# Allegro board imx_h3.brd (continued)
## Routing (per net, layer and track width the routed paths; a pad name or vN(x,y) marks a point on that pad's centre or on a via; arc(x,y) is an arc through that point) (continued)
GND: length 1234.3
  TOP w0.1: 93.23,71.44 92.46,71.44 v1(92.41,71.49) 92.36,71.44 R122.2 ; 93.23,71.44 93.23,71.53 93.24,71.54 FL6.1 ; 93.23,71.44 93.23,71.2 FL7.2 ; 88.45,68.63 88.45,69.09 ; 88.45,69.09 87.75,69.09 v1(87.73,69.1) ; 88.45,69.09 88.45,69.56 ; J13.60 95.91,64.93 ; J13.60 97.68,64.63 v1(97.72,64.68) ; J13.60 94.62,64.63 ; v1(97.51,59.16) 96.98,58.63 J13.36 94.62,58.63 94.02,58.03 C135.2 ; 76.26,87.95 J23.2 ; J23.2 77.25,88.94 ; J23.2 78.23,87.95 ; J23.2 77.25,86.97 ; J13.48 97.62,61.63 v1(97.68,61.69) ; v1(91.7,37.36) 91.7,37.5 92.38,38.19 93.16,38.19 93.17,38.2 93.91,38.2 R57.2 ; J13.SH6 99.14,74.21 ; J13.SH6 98.4,74.21 ; J13.SH6 98.77,76.71 ; J13.SH6 98.77,73.03 v1(99.78,72.03) ; SW5.2 87.16,1.57 ; SW5.2 v1(86.11,0.91) ; SW5.2 87.92,0.91 ; 105.09,70.67 C263.2 105.09,71.6 ; FL8.2 106.01,87.42 v1(106.04,87.39) ; 93.23,80.95 92.39,80.95 v1(92.31,81.03) ; 93.23,80.95 93.23,80.69 FL3.2 ; 93.23,80.95 FL2.1 ; SW3.2 SW3.4 SW7.2 ; SW3.2 93.53,103.61 ; SW3.2 92.57,104.27 ; FL5.2 93.22,75.84 93.22,76.19 ; FL5.2 93,75.82 ; FL5.2 93.47,75.82 ; 93.22,76.19 92.23,76.19 v1(92.19,76.15) ; 93.22,76.19 FL4.1 ; 104.46,55.86 C257.2 ; C257.2 104.46,56.79 ; C257.2 104.93,56.32 ; J13.93 102.72,78.13 103.07,77.79 103.07,77.36 v1(103.13,77.3) ; v1(105.34,98.06) 105.7,97.7 S1.4 ; 52.22,45.05 C66.2 52.69,44.58 ; C108.1 66.51,18.45 R43.2 ; C108.1 66.57,17.53 v1(66.15,17.1) ; C108.1 67.04,18.38 ; C108.1 66.57,18.85 ; 75.78,77.86 C243.2 ; C243.2 76.72,77.86 ; C243.2 76.25,78.33 ; v1(105.34,103.98) 106.66,103.98 ; 106.66,103.98 106.58,103.91 102.06,103.91 SW7.2 ; 106.66,103.98 SW7.4 ; v1(62.64,44.75) 62.2,45.2 61.45,45.2 61.2,44.95 v1(61.02,44.95) ; v1(24.45,27.44) 23.79,28.1 J20.52 ; T1.8 55.82,17.83 ; T1.8 55.82,16.05 ; T1.8 56.71,16.94 ; v1(92.78,69.04) 92.78,69.04 92.78,69.04 93.17,69.43 FL7.1 ; v1(12.99,50.22) 12.98,50.23 12.98,51.79 C217.2 12.97,50.9 12.97,50.9 ; v1(98.2,79.78) 98.77,80.35 J13.SH7 98.77,80.56 ; FL7.1 93.49,69.43 ; FL7.1 93.25,69.05 ; J20.52 J20.50 ; J20.52 22.6,28.1 ; J20.52 23.75,27.64 ; J20.50 J20.48 22.8,29.7 v1(22.37,29.26) ; J20.50 22.67,28.9 22.41,28.64 v1(22.38,28.64) ; FL4.1 92.98,76.49 ; FL4.1 93.45,76.49 ; 77.76,48.42 C2.2 78.23,47.95 ; 12.43,62.91 13.21,62.91 ; 13.21,62.91 13.21,61.17 ; 13.21,62.91 13.21,64.65 ; J20.8 24.49,48.9 25.06,49.47 25.06,49.72 v1(25.11,49.76) ; 111.42,11.19 Y8.2 ; Y8.2 112.17,12.04 ; Y8.2 110.67,12.04 ; Y8.2 111.07,12.39 C148.2 111.31,13.46 v1(111.58,13.19) ; Y8.2 111.42,12.89 ; 93.06,48.94 C262.2 92.59,49.41 ; 76.48,57.77 C246.2 76.48,56.84 ; 82.52,36.76 C277.2 81.08,36.76 ; J13.SH3 99.14,60.56 ; J13.SH3 98.77,63.07 ; J13.SH3 98.5,60.56 98.2,60.86 v1(98.2,61.32) ; J13.SH3 98.77,58.06 ; 71.1,40.4 C113.2 71.1,42.23 ; v1(99.48,68.57) 99.43,68.57 98.77,69.23 J13.SH5 ; 94.02,57.49 C135.2 ; C135.2 93.55,57.96 ; C135.2 94.49,57.96 ; 70.8,52.25 C22.2 70.8,51.31 ; 109.02,7.9 108.55,7.9 108.55,8.36 ; v1(105.27,1.05) 105.6,1.05 105.77,0.88 SW8.1 ; TP3.1 32.73,70.42 ; TP3.1 30.91,70.42 ; TP3.1 31.82,71.33 ; TP3.1 31.82,69.51 ; 26.98,24.86 C239.2 27.91,24.86 ; T1.14 60.32,11.1 ; T1.14 57.93,11.1 ; T1.14 59.13,9.91 ; T1.14 59.13,12.29 ; 108.64,25.98 C300.2 108.64,27.42 ; C256.2 104.33,59.29 104.68,58.94 v1(105.03,58.94) ; C256.2 104.8,59.31 ; C256.2 104.33,59.77 ; SW6.1 98.75,0.89 98.64,1 v1(98.53,1) ; 93.23,83.41 92.26,83.41 v1(92.23,83.38) ; 93.23,83.41 93.23,83.06 FL2.2 ; 93.23,83.41 FL1.1 ; 69.36,49.07 C10.2 ; C10.2 69.36,50 ; C10.2 69.83,49.53 ; J17.3 63.86,31.79 ; J17.3 63.86,29.99 ; J17.3 62.96,30.89 ; J17.3 64.76,30.89 ; C236.2 81.95,8.47 ; C236.2 83.12,7.62 ; C236.2 80.78,7.62 ; 64.16,38.64 64.91,37.88 64.91,37.75 ; v1(99.9,80.42) 100.11,80.64 101.63,80.64 ; FL4.2 93.22,78.65 ; 93.22,78.65 93.22,78.91 FL3.1 ; 93.22,78.65 92.61,78.65 v1(92.51,78.54) ; 66.77,41.72 C100.2 ; C100.2 66.77,42.65 ; C100.2 67.24,42.19 ; 103.96,93.89 S1.3 ; S1.3 105.7,92.36 v1(105.97,92.09) ; S1.3 107.44,93.89 ; S1.3 105.7,94.92 ; v1(61.06,54.37) 61.44,54.74 R58.2 ; v1(98.2,55.54) 98.08,55.54 97.98,55.63 J13.24 ; 75.78,78.99 C244.2 ; C244.2 76.25,78.52 ; C244.2 76.72,78.99 ; R80.2 87.54,44.17 v1(87.06,43.69) ; J13.SH4 98.77,66.87 ; J13.SH4 98.4,65.45 ; J13.SH4 98.77,64.03 ; J13.SH4 99.08,65.45 v1(99.34,65.72) ; J13.23 103.26,55.63 v1(103.28,55.66) ; J13.30 97.98,57.13 98.07,57.05 v1(98.3,57.05) ; 104.65,79.42 104.66,79.41 ; 45.92,59.51 46.39,59.51 ; 45.92,59.51 45.81,59.51 45.41,59.91 v1(45.06,59.91) ; 45.92,59.51 45.92,59.04 ; C234.2 23.15,22.05 ; C234.2 24.32,21.2 ; C234.2 21.99,21.2 ; 98.4,80.56 98.77,80.56 ; 98.77,80.56 98.77,78.05 ; 79.26,48.34 C1.2 79.85,49.25 ; R123.2 88.31,72.08 ; R123.2 88.31,71.15 ; R123.2 88.29,71.59 87.13,71.59 v1(86.08,72.65) ; R123.2 87.84,71.62 ; 92.99,85.48 FL1.2 ; FL1.2 93.47,85.48 ; FL1.2 93.23,85.76 v1(93.59,86.12) ; 25.19,39.04 25.34,38.89 25.34,38.84 v1(25.39,38.84) ; FL8.1 103.59,87.66 ; FL8.1 103.12,87.42 v1(102.96,87.27) ; FL8.1 103.59,87.18 ; 99.83,7.53 C134.2 101.65,7.53 ; 69.86,39.11 C117.2 71.68,39.11 ; C258.2 104.42,53.58 ; C258.2 104.89,53.11 ; C258.2 C259.2 104.4,52.35 C255.2 104.4,51.05 v1(104.7,50.75) ; SW7.4 107.89,104.27 ; SW7.4 105.99,104.27 ; SW7.4 106.94,103.61 ; 98.77,51.71 J13.SH2 98.4,54.22 ; 78,55.92 C8.2 78,54.98 ; 93,71.77 FL6.1 ; FL6.1 93.48,71.77 ; FL2.2 93.46,83.05 ; FL2.2 92.99,83.05 ; 83.2,6.6 C241.2 83.2,5.66 ; 103.96,96.42 S1.4 ; S1.4 107.44,96.42 ; S1.4 105.7,95.39 ; FL6.2 93.48,73.52 ; FL6.2 93,73.52 ; FL6.2 93.23,73.53 93.23,73.9 ; 92.99,83.72 FL1.1 ; FL1.1 93.47,83.72 ; 93.01,71.18 FL7.2 ; FL7.2 93.49,71.18 ; J13.42 97.59,60.13 97.61,60.16 v1(97.65,60.16) ; SW7.2 101.69,103.61 ; SW7.2 102.64,104.27 ; J13.SH5 99.14,69.32 ; J13.SH5 98.4,69.32 ; 24.58,49.72 23.77,49.72 24.09,50.04 24.82,50.04 24.91,50.13 24.91,50.15 25.01,50.25 ; 113.25,12.74 TP5.1 ; TP5.1 112.33,13.65 ; TP5.1 114.16,13.65 ; TP5.1 113.25,14.56 ; 72.74,45.92 C23.2 72.27,46.38 ; 114.89,24.39 L4.2 ; L4.2 115.45,23.74 ; L4.2 116,24.39 ; L4.2 115.45,25.03 ; 72.87,48.78 C21.2 72.87,49.71 ; J13.SH1 98.77,50.75 ; J13.SH1 98.4,49.33 ; J13.SH1 99.14,49.33 ; J16.2 111.86,28.9 ; J16.2 110.05,28.9 ; J16.2 110.96,27.99 ; J16.2 110.96,29.8 ; J13.54 97.58,63.13 v1(97.59,63.15) ; 104.66,78.64 104.67,78.63 ; 83.57,10.16 C237.2 82.73,11.32 ; 121.97,7.96 R208.1 120.53,7.96 ; SW8.1 106.42,1.54 ; SW8.1 107.18,0.88 ; 23.15,22.6 C235.2 ; C235.2 23.15,24.3 ; C235.2 24.32,23.45 ; 98.4,85.44 J13.SH8 ; J13.SH8 99.14,85.44 ; J13.SH8 v1(98.77,87.06) ; 78.93,55.15 C78.2 79.53,54.24 ; 70.54,45.39 C13.2 ; C13.2 71.01,45.86 ; C13.2 70.54,46.33 ; 78.76,37.72 D17.A 79.53,36.91 ; 70.21,78.06 C294.2 70.68,77.59 ; v1(80.14,47.71) 80.5,48.07 C136.2 ; 104.46,47.53 C260.2 ; C260.2 104.46,48.47 ; C260.2 104.93,48 ; 43.63,9.91 T1.13 ; T1.13 42.44,11.1 ; T1.13 43.63,12.29 ; 80.93,47.6 C136.2 ; C136.2 80.93,48.54 ; R148.2 R150.2 81.46,39.48 v1(81.65,39.28) ; v1(109.52,8.69) 109.82,8.39 C149.2 110.05,9.61 Y8.4 ; 35.27,59.19 C221.2 35.27,57.36 ; 109.07,9.84 Y8.4 ; Y8.4 110.57,9.84 ; Y8.4 109.82,8.99 ; 57.92,47.24 v1(57.87,47.28) ; 78.39,56.39 C245.2 77.92,56.86 ; C121.2 65.59,41.64 ; C121.2 66.31,41.05 ; C121.2 64.86,41.05 ; v1(92.41,73.79) 92.48,73.72 93.06,73.72 93.23,73.9 ; 66.74,32.75 C129.2 ; FL5.1 93.47,74.07 ; FL5.1 93,74.07 ; FL5.1 93.23,73.9 ; 60.65,34.71 C128.2 61.56,35.31 ; 68.26,38.33 C116.2 68.86,39.06 ; 67.94,56.42 C6.2 67.94,55.48
  TOP w0.15: 105.84,7.47 106.36,7.47
  TOP w0.2: 53.8,44.93 C74.2
  TOP w0.25: C90.2 56.67,49.17 56.67,49.38 56.32,49.73 C72.2
  TOP w0.3: 98.08,53 97.72,52.63 J13.12 ; 98.08,53 98.08,51.78 97.44,51.13 J13.6 94.38,51.13 C279.2 ; 98.08,53 98.08,53.53 98.26,53.7 ; 27.43,57.65 27.43,57.65 26.73,58.35 U42.2 ; 27.43,57.65 v1(27.59,57.65) ; 27.43,57.65 C292.2 ; v1(105.79,74.66) 105.76,74.63 C254.2 ; v1(63.9,47.6) 63.9,47.55 63.45,48 63.45,48.2 63.35,48.3 C96.2 ; C100.2 66.85,42.27 ; 66.85,42.27 66.75,42.27 66.23,42.79 C69.2 ; 66.85,42.27 67.08,42.04 v1(67.48,42.04) ; 63.2,52.54 62.71,52.06 v1(62.67,52.06) ; 56.53,14.31 56.45,14.4 T1.7 ; v1(98.65,57.55) 98.65,57.38 98.77,57.26 J13.SH2 98.26,53.7 ; C66.2 52.23,44.59 52.87,44.59 53.04,44.76 v1(53.05,44.75) ; C300.2 v1(107.65,26.7) 107.6,26.65 ; 27.8,64.45 27.52,64.17 C293.2 ; C16.2 77.95,51.17 ; C16.2 78,51.99 C9.2 78.83,53.06 v1(78.93,53.16) C78.2 78.96,54.26 v1(78.96,55.45) C8.2 77.92,55.53 77.92,56.38 ; C16.2 78.4,51.94 v1(78.69,51.65) ; 77.95,51.17 77.94,51.16 77.94,50.44 C11.2 ; 77.95,51.17 78.42,51.65 v1(78.69,51.65) ; C113.2 71.4,41.02 R42.2 71.68,39.72 C112.2 72.26,39.56 71.88,39.18 v1(71.88,38.6) ; 57.92,47.24 57.15,47.24 ; C289.2 105.92,72.1 v1(105.93,72.09) ; 53.68,44.19 53.65,44.19 53.28,44.55 53.26,44.55 53.06,44.76 ; C4.2 v1(75.89,42.32) 75.84,42.28 C92.2 74.96,42.25 C5.2 ; v1(56.64,40.03) 56.64,39.39 C70.2 ; C12.2 78.43,51.18 78.69,50.93 ; C76.2 54.52,46.29 54.51,46.28 54.62,46.28 54.66,46.32 C77.2 54.22,47.44 54.22,47.84 ; 78.69,50.93 v1(78.69,51.65) ; 78.69,50.93 v1(78.76,50.85) ; v1(102.4,86.19) 102.45,86.23 102.45,86.75 v1(102.96,87.27) ; 58.73,40.79 58.67,40.73 58.67,40.32 ; C10.2 69.65,49.25 v1(69.95,49.25) ; v1(57.87,47.28) 57.93,47.34 C62.2 59.56,47.34 C83.2 59.44,47.42 ; J20.9 14.04,48.5 C214.2 C151.2 13.17,48.62 v1(13.7,49.15) ; 13.21,62.91 13.46,62.91 14.2,63.64 ; J20.24 22.13,39.3 22.05,39.22 21.95,39.22 v1(21.74,39.01) ; 56.19,50.5 55.5,49.81 v1(55.5,49.66) ; 56.19,50.5 56.17,50.5 C81.2 ; 56.19,50.5 56.34,50.5 56.3,50.47 C72.2 55.57,49.73 v1(55.5,49.66) ; C20.2 66.87,47.51 v1(66.38,47.51) ; C125.2 62.05,39.6 C111.2 ; v1(78.76,50.85) 78.38,50.85 C11.2 ; v1(78.76,50.85) 78.64,50.74 78.64,50.29 v1(78.58,50.24) ; 98.26,53.7 97.82,54.13 J13.18 ; v1(61.06,54.37) 61.09,54.34 61.09,53.92 C87.2 ; v1(73.6,47.79) 73.39,47.79 72.75,47.15 C19.2 72.75,46.39 C23.2 ; C241.2 82.69,6.13 82.67,6.11 v1(82.53,6.11) ; D44.1 71.47,74.9 v1(70.79,74.22) ; v1(101.42,6.72) 100.74,7.4 C134.2 ; C114.2 68.26,40.16 C105.2 68.38,39.17 C116.2 68.38,38.94 69.52,38.94 ; 69.52,38.94 69.72,38.73 v1(69.72,38.61) ; 69.52,38.94 70.6,38.94 C117.2 ; 77.71,37.94 v1(77.64,38) ; 77.71,37.94 77.85,37.79 78.58,37.79 78.64,37.73 79.52,37.73 D17.A ; 77.71,37.94 C202.2 ; J20.13 13.93,46.9 13.85,46.98 13.85,46.92 v1(13.84,46.92) ; v1(103.3,8.28) 103.31,8.29 U34.13 103.31,9.9 U34.25 105.91,12.5 U34.23 107.9,12.5 v1(108.35,12.95) ; C34.2 107.48,16.19 v1(107.88,16.58) ; v1(28.15,24.8) 28.2,24.75 27.56,24.75 C239.2 ; v1(105.13,56.42) 104.56,56.42 C257.2 ; C290.2 94.46,47.14 94.91,47.58 94.91,47.98 v1(95.12,48.2) ; v1(55.5,49.66) 55.61,49.54 C65.2 55.31,48.77 C64.2 54.36,48.77 54.22,48.62 54.22,47.84 ; v1(105.53,55.02) 105.41,55.02 105.01,55.42 104.58,55.42 104.58,55.03 104.38,54.83 C264.2 ; v1(80.44,74.78) 80.65,75 80.65,75 81.14,75.49 C274.2 ; v1(69.8,36.23) 69.8,36.15 69.37,35.71 69.12,35.71 68.95,35.54 68.56,35.54 C63.2 ; C246.2 77.04,57.31 v1(77.11,57.38) ; TVS2.1 20.87,17.29 v1(20.23,17.29) ; 108.55,7.9 108.55,7.45 108.66,7.35 108.66,7.14 C205.2 109.01,7.49 v1(109.28,7.76) ; 54.12,47.95 54.22,47.84 ; 24.58,49.72 J20.8 ; C84.2 59.78,51.43 59.78,51.48 v1(60.26,51.96) ; v1(27.85,20.5) 27.52,20.82 C240.2 ; 28.55,63.43 28.55,64.05 28.42,64.17 ; v1(72.26,49.86) 72.37,49.86 72.7,50.2 C18.2 72.84,49.28 C21.2 ; C11.2 78.39,50.43 v1(78.58,50.24) ; 61.5,49 C80.2 61.51,49.09 61.05,49.55 61.05,50.43 v1(61.09,50.47) 61.76,50.47 C98.2 ; v1(25.11,50.51) 25.08,50.49 25.08,50.32 25.01,50.25 25.01,50.09 24.62,49.7 J20.6 ; v1(78.58,50.24) 78.79,50.24 79.26,49.77 C1.2 79.25,49.25 79.25,48.33 79.07,48.15 v1(78.58,48.15) 77.96,48.15 C2.2 v1(77.76,47.3) C3.2 77.76,45.77 v1(77.72,45.72) ; 77.92,56.38 v1(78.39,55.91) ; 77.92,56.38 C245.2 ; C94.2 62.76,47.71 62.75,47.7 62.75,47.61 62.41,47.27 v1(61.85,47.27) ; 58.67,40.32 59.05,40.32 C86.2 ; 58.67,40.32 v1(58.62,40.28) ; v1(49.23,46.37) 49.23,46.46 49.6,46.84 C67.2 50.44,47.41 51.12,47.41 51.35,47.19 v1(51.49,47.19) ; C89.2 64.23,46.77 v1(64.65,46.35) ; v1(72.16,45.61) 70.79,45.61 C13.2 ; C7.2 71.02,43.75 71.34,44.07 v1(71.34,44.33) ; 92.45,50.14 92.52,50.22 C278.2 ; 92.45,50.14 92.48,50.14 93.06,49.57 C262.2 ; 92.45,50.14 v1(92.39,50.14) ; C22.2 71.61,51.78 v1(71.62,51.77) ; C90.2 57.72,48.75 C60.2 57.84,49.09 v1(57.84,49.64) ; J20.14 24.7,46.5 24.89,46.68 25.11,46.68 v1(25.11,46.68) ; v1(98.03,48.05) 98.03,48.3 98.77,49.04 J13.SH1 ; J20.26 22.29,38.5 22.17,38.38 21.73,38.38 v1(21.71,38.36) ; v1(71.43,77.96) 71.39,77.91 71.16,77.91 71.01,78.06 C294.2 ; v1(99.71,10.61) 99.81,10.61 100.01,10.41 C35.2 100.36,11.21 R18.1 99.93,11.22 99.81,11.34 v1(99.71,11.34) ; C263.2 v1(105.83,71.13) ; C6.2 67.94,55.95 67.94,55.12 67.98,55.07 v1(67.98,55)
  TOP w0.5: v1(65.34,44.97) 64.84,44.97 63.96,45.85 ; 65.06,41.72 64.72,41.38 C101.2 ; 65.06,41.72 65.06,41.57 C121.2 ; 65.06,41.72 v1(65.06,42.14) ; C277.2 81.8,38.04 v1(81.81,38.05) ; 53.05,44.75 53.22,44.75 53.68,44.3 53.68,44.19 C75.2 C74.2 53.65,44.91 53.5,44.76 53.06,44.76 53.05,44.75 ; 53.05,44.75 v1(53.05,44.75) ; U29.2 34.25,65.96 33.66,65.37 v1(33.48,65.37) ; C295.2 18.19,14.78 v1(17.54,15.44) 17.54,15.44 C107.2 ; C125.2 63.01,39.23 C126.2 ; v1(32.6,67.09) 32.6,67.02 32.74,67.16 32.74,67.16 32.76,67.21 32.8,67.29 32.85,67.36 32.92,67.42 32.92,67.42 33,67.47 33.08,67.49 33.13,67.5 33.35,67.72 C222.2 ; 63.96,45.85 64.14,45.85 v1(64.65,46.35) ; 63.96,45.85 C79.2 63.66,45.56 62.94,44.84 62.64,44.84 v1(62.64,44.75) ; v1(17.12,14.96) 17.05,14.9 R20.2 ; v1(36.06,58.77) 35.77,58.77 35.28,58.28 C221.2 ; 58.54,48.81 v1(58.6,48.81) ; 58.54,48.81 58.65,48.93 v1(58.65,49.71) 58.58,49.64 v1(57.84,49.64) ; 58.54,48.81 58.47,48.81 58.47,48.93 58.46,48.91 58.01,48.91 C60.2 ; v1(67.39,33.35) 67.19,33.15 67.13,33.15 66.74,32.75 ; 62.78,32.03 C131.2 62.74,32.83 62.35,33.22 C132.2 62.35,34.56 62.15,34.76 62.15,35.4 C130.2 ; v1(60.38,34.5) 60.38,35.04 C128.2 ; 64.16,38.64 C119.2 ; C119.2 63.91,38.76 63.66,39.01 63.31,39.01 C126.2 ; C119.2 64.03,38.31 64.17,38.17 64.31,38.17 64.85,37.64 C127.2 ; v1(53.1,50.41) 53.1,51.13 ; 53.1,51.13 53.1,51.13 C71.2 ; 53.1,51.13 53.06,51.17 ; v1(45.06,59.91) 44.93,59.78 C103.2 v1(41.82,59.78) 41.75,59.85 ; C285.2 C284.2 ; C284.2 30.95,60.73 30.7,60.47 30.7,60.12 C286.2 ; C284.2 30.51,61.35 v1(30.44,61.35) ; v1(121.25,8.95) R208.1 ; v1(121.25,8.95) 121.3,8.9 ; v1(121.25,8.95) 121.25,9.05 ; v1(62.75,40.45) 62.75,40.13 63.02,39.85 63.02,39.3 C126.2 ; v1(31.98,66.01) 32.05,65.94 C224.1 R175.2 ; v1(82.83,34.77) 82.45,34.39 C276.2 82.41,34.14 C275.2 ; C235.2 21.8,23.45 21.6,23.65 21.6,24.4 20.65,25.35 19.87,25.35 v1(19.86,25.34) ; C124.2 63.87,37.13 64.17,37.43 64.7,37.43 C127.2 ; C123.2 67.41,35.53 67.51,35.44 68.04,35.44 C63.2 ; 57.02,45.71 57.02,46.36 C57.2 57.09,47.19 v1(57.09,47.2) ; C127.2 64.91,37.75 ; v1(81.21,9.16) 81.47,9.16 82.47,10.16 C237.2 82.73,8.4 C236.2 81.95,7.1 81.42,6.57 v1(81.31,6.57) ; v1(70.26,40.85) 70.44,40.85 70.91,41.31 C113.2 ; v1(115.45,25.35) 115.45,24.39 L4.2 ; TVS1.1 v1(17.19,18.56) ; 22.77,21.44 v1(21.48,21.44)
  GND1 w0.1: T1.14 60.32,11.1 ; T1.14 59.13,9.91 ; T1.14 59.13,12.29 ; T1.14 57.93,11.1 ; 43.63,9.91 T1.13 ; T1.13 42.44,11.1 ; T1.13 43.63,12.29 ; 110.05,28.9 J16.2 ; J16.2 110.96,29.8 ; J16.2 111.86,28.9 ; J16.2 110.96,27.99 ; 62.96,30.89 J17.3 ; J17.3 63.86,29.99 ; J17.3 64.76,30.89 ; J17.3 63.86,31.79 ; T1.8 55.82,17.83 ; T1.8 56.71,16.94 ; T1.8 55.82,16.05 ; 112.33,13.65 TP5.1 ; TP5.1 113.25,14.56 ; TP5.1 114.16,13.65 ; TP5.1 113.25,12.74 ; 77.25,86.97 J23.2 ; J23.2 78.23,87.95 ; J23.2 77.25,88.94 ; J23.2 76.26,87.95 ; 30.91,70.42 TP3.1 ; TP3.1 32.73,70.42 ; TP3.1 31.82,71.33 ; TP3.1 31.82,69.51 ; TP4.1 5.64,2.81 ; TP4.1 5.64,0.99 ; TP4.1 4.73,1.9 ; TP4.1 6.55,1.9 ; 61.4,45 61.4,45.05 61.55,45.2 62.2,45.2 62.25,45.15
  GND1 w0.3: J5.3 11.88,5.57 ; J5.3 9.38,4.66 ; J5.3 14.39,4.66 ; J5.3 11.88,3.75 ; 56.86,14.84 56.42,14.4 T1.7
  INT1 w0.1: J17.3 63.86,31.79 ; J17.3 63.86,29.99 ; J17.3 64.76,30.89 ; J17.3 62.96,30.89 ; 5.64,0.99 TP4.1 ; TP4.1 4.73,1.9 ; TP4.1 5.64,2.81 ; TP4.1 6.55,1.9 ; TP3.1 31.82,71.33 ; TP3.1 32.73,70.42 ; TP3.1 30.91,70.42 ; TP3.1 31.82,69.51 ; 110.05,28.9 J16.2 ; J16.2 110.96,29.8 ; J16.2 111.86,28.9 ; J16.2 110.96,27.99 ; J23.2 77.25,88.94 ; J23.2 76.26,87.95 ; J23.2 77.25,86.97 ; J23.2 78.23,87.95 ; 57.93,11.1 T1.14 ; T1.14 59.13,9.91 ; T1.14 59.13,12.29 ; T1.14 60.32,11.1 ; T1.13 43.63,12.29 ; T1.13 42.44,11.1 ; T1.13 43.63,9.91 ; T1.8 55.82,17.83 ; T1.8 55.82,16.05 ; T1.8 56.71,16.94 ; 113.25,12.74 TP5.1 ; TP5.1 112.33,13.65 ; TP5.1 114.16,13.65 ; TP5.1 113.25,14.56
  INT1 w0.3: T1.7 56.6,14.4 56.69,14.31 ; 11.88,3.75 J5.3 ; J5.3 9.38,4.66 ; J5.3 14.39,4.66 ; J5.3 11.88,5.57 ; v1(83.65,56.9) 83.65,57 84.98,58.33 85.09,58.33 88.51,61.75 88.55,61.75 89.46,62.67 90.26,62.67 93.01,65.42 v1(93.01,65.43)
  PWR w0.1: T1.13 43.63,12.29 ; T1.13 43.63,9.91 ; T1.13 42.44,11.1
  GND2 w0.1: J23.2 78.23,87.95 ; J23.2 77.25,86.97 ; J23.2 77.25,88.94 ; J23.2 76.26,87.95 ; 106.61,91.45 v1(105.97,92.09) ; 106.61,91.45 106.61,87.95 v1(106.04,87.39) ; 106.61,91.45 106.61,96.8 v1(105.34,98.06) ; 110.05,28.9 J16.2 ; J16.2 111.86,28.9 ; J16.2 110.96,29.8 ; J16.2 110.96,27.99 ; 62.2,45.2 61.55,45.2 61.3,44.95 v1(61.02,44.95) 61.22,44.75 ; TP4.1 6.55,1.9 ; TP4.1 5.64,0.99 ; TP4.1 4.73,1.9 ; TP4.1 5.64,2.81 ; TP5.1 114.16,13.65 ; TP5.1 112.33,13.65 ; TP5.1 113.25,14.56 ; TP5.1 113.25,12.74 ; 57.93,11.1 T1.14 ; T1.14 59.13,12.29 ; T1.14 60.32,11.1 ; T1.14 59.13,9.91 ; J17.3 64.76,30.89 ; J17.3 63.86,29.99 ; J17.3 62.96,30.89 ; J17.3 63.86,31.79 ; TP3.1 32.73,70.42 ; TP3.1 31.82,69.51 ; TP3.1 30.91,70.42 ; TP3.1 31.82,71.33 ; 42.44,11.1 T1.13 ; T1.13 43.63,9.91 ; T1.13 43.63,12.29 ; T1.8 55.82,17.83 ; T1.8 55.82,16.05 ; T1.8 56.71,16.94
  GND2 w0.3: 11.88,3.75 J5.3 ; J5.3 11.88,5.57 ; J5.3 9.38,4.66 ; J5.3 14.39,4.66 ; 56.77,14.59 56.59,14.4 T1.7
  BOTTOM w0.1: C139.2 61.78,29.45 ; C139.2 61.37,29.51 61.37,30.11 v1(61.38,30.12) ; C139.2 60.95,29.81 C138.2 59.83,29.81 v1(59.22,29.2) ; C139.2 61.31,29.92 ; Q16.2 82.71,84.05 ; Q16.2 82.2,84.64 ; Q16.2 82.2,83.45 ; Q16.2 81.7,84.05 ; v1(99.99,75.84) 100.06,75.84 100.2,75.71 101.15,75.71 ; 58.24,47.14 58.24,46.84 58.55,46.84 ; U3.25 33.88,45.22 35.67,47 v1(35.67,47.12) ; U3.25 33.84,45.19 32.12,43.49 32.12,43.46 31.75,43.08 30.34,43.08 C27.2 ; U3.25 35.56,43.49 36.25,43.49 v1(36.32,43.56) 36.34,43.54 37.32,43.54 C251.2 37.48,43.58 C252.2 ; U3.25 33.84,45.27 32.27,46.84 32.27,47.5 v1(32.13,47.63) ; 19.95,65.37 U4.62 ; U4.62 22.86,65.37 ; U4.62 21.41,66.82 ; 94.92,57.78 C184.2 95.83,58.38 ; v1(33.84,38.32) 33.84,38.32 33.81,38.3 R136.2 ; C73.2 21.12,47.88 ; C73.2 20.53,46.96 ; C73.2 20.53,48.79 ; 83.48,10.72 82.33,10.72 82.3,10.7 ; 83.48,10.72 83.1,11.1 83.1,12.05 ; 83.48,10.72 83.53,10.72 ; 59.18,11.1 59.18,13.59 56,16.76 ; 57.14,49.24 57.45,49.24 ; 57.45,49.24 57.45,49.54 ; 57.45,49.24 57.45,48.93 ; 57.45,49.24 57.75,49.24 ; 99.21,40.1 R130.2 ; R130.2 99.68,40.57 ; R130.2 100.14,40.1 ; U41.5 U41.6 ; U40.7 13.01,28.93 13.2,29.11 v1(13.2,29.15) ; v1(35.04,50.29) 35.07,50.29 35.07,50.21 35.28,50 R16.1 ; T1.8 56,16.76 ; T1.8 55.82,17.83 ; T1.8 56.71,16.94 ; T1.8 55.82,16.05 ; T1.8 53.56,19.21 C31.2 ; 56,16.76 56,15.84 T1.7 ; 80.9,37.1 C201.2 82.72,37.1 ; 22.11,59.43 C160.2 21.64,58.97 ; 24.94,56.97 C165.2 26.77,56.97 ; 18.51,63.9 U4.61 16.91,62.37 ; 33.4,6.36 L23.1 ; L23.1 33.96,7.01 ; L23.1 32.84,7.01 ; 71.12,40.42 C15.2 71.12,42.24 ; C137.2 57.83,33.2 57.43,33.6 v1(57.43,33.56) ; C137.2 57.98,32.73 ; C137.2 57.98,33.67 ; v1(104.68,49.94) 104.68,49.93 ; v1(104.68,49.94) U15.87 ; v1(104.68,49.94) U15.95 ; 104.68,49.93 U15.86 ; 104.68,49.93 U15.96 ; 83.58,10.72 83.2,10.35 83.2,9.45 ; 83.58,10.72 83.53,10.72 ; 83.58,10.72 U33.9 ; 76.7,85.47 C200.1 77.17,85.94 ; Q9.2 74.22,35.17 ; Q9.2 73.14,35.17 72.66,34.69 72.66,34.21 v1(72.68,34.19) ; Q9.2 73.63,34.67 ; v1(42.1,15.95) 42.85,15.95 43.05,16.15 ; 78.31,85.19 C207.2 78.78,84.73 ; 58.24,48.74 U1.K11 57.94,48.44 ; C122.2 67.58,40.44 ; C122.2 66.98,41.35 ; C122.2 66.98,39.53 ; 53.45,44.74 53.45,44.44 53.75,44.44 ; 52.64,51.14 52.64,50.84 52.95,50.84 ; 99.61,57.38 Y5.4 ; Y5.4 99.61,59.08 ; Y5.4 98.65,58.23 v1(98.07,58.81) ; Y5.4 100.35,58.23 ; 74.36,47.71 U2.E7 74.7,48.06 ; C153.2 71.88,40.01 v1(71.88,38.6) ; C153.2 71.96,39.63 ; C153.2 71.96,40.56 ; C153.2 71.49,40.09 ; 25.76,68.29 C190.2 25.76,69.22 ; 14.37,49.12 C102.2 14.37,50.94 ; C172.1 29.04,62.62 ; C172.1 28.11,62.62 ; C172.1 28.58,61.68 v1(28.42,61.53) ; 56.64,48.74 U1.K9 56.34,48.44 ; U15.86 v1(105.5,49.92) ; U15.86 U15.78 v1(103.89,50.74) U15.88 103.49,50.33 U15.96 ; U15.86 105.09,50.34 v1(105.49,50.75) U15.76 v1(106.28,50.74) U15.84 v1(106.29,49.94) 105.89,49.54 U15.94 U15.104 v1(104.7,49.12) U15.96 ; 95.77,39.09 95.77,39.47 95.92,39.62 95.92,39.64 v1(96,39.72) ; 70.7,45.66 U2.B2 70.01,45.66 ; 62.74,41.24 63.05,41.24 63.05,40.93 ; 70.75,39.75 C118.2 71.66,39.16 ; 35.93,65.51 C52.2 R27.2 ; R11.2 43.06,16.44 ; R11.2 42.59,15.97 ; R11.2 43.05,15.98 43.05,16.15 ; TP4.1 6.55,1.9 ; TP4.1 5.64,2.81 ; TP4.1 4.73,1.9 ; TP4.1 5.64,0.99 ; J17.3 63.86,31.79 ; J17.3 62.96,30.89 ; J17.3 64.76,30.89 ; 58.24,47.33 U1.J11 ; U1.J11 58.55,47.63 ; U1.J11 57.94,47.63 ; 57.14,46.84 57.45,46.84 57.45,47.14 ; v1(103.28,55.66) 103.28,55.74 102.98,56.03 101.21,56.03 ; 43.63,9.91 T1.13 ; T1.13 43.63,12.29 ; T1.13 42.44,11.1 ; 77.74,85.11 D43.3 77.74,83.42 ; v1(37.23,30.73) 37.1,30.6 36.86,30.6 36.79,30.53 36.73,30.53 36.49,30.29 36.49,30.24 36.3,30.04 ; 24.39,46.69 24.86,46.69 ; 24.39,46.69 23.93,46.69 ; 24.39,46.69 24.39,46.22 ; 31.76,49.41 31.75,49.42 C33.2 ; 31.76,49.41 33.22,49.41 C29.2 ; 31.76,49.41 C32.2 ; v1(28.55,38.78) 28.54,38.77 28.54,38.4 28.33,38.19 R142.2 ; v1(96.77,7.38) 96.8,7.41 96.8,8.13 R131.2 ; U15.96 v1(103.88,49.13) U15.106 ; 112.33,13.65 TP5.1 ; TP5.1 114.16,13.65 ; TP5.1 113.25,14.56 ; TP5.1 113.25,12.74 ; 36.3,29.18 R177.2 36.77,29.65 ; 43.05,16.15 43.05,16.53 43.06,16.54 ; 82.76,75.54 C273.2 82.3,75.07 ; 39.74,33.5 C146.1 ; C146.1 39.28,33.97 ; C146.1 40.21,33.97 ; C146.1 39.7,33.93 39.16,33.93 v1(39.08,33.85) ; v1(26.95,61.12) 27.19,61.36 Y4.2 ; 34.36,29.35 C210.2 34.36,28.42 ; C171.2 29.03,65.65 ; C171.2 28.1,65.65 ; C171.2 28.56,66.23 28.84,66.5 v1(28.84,66.66) ; 71.99,58.99 72.46,58.99 72.46,59.46 ; 84.84,55.32 C185.2 83.01,55.32 ; 69.37,35.65 69.38,35.64 ; 69.37,35.65 69.37,35.71 ; 69.37,35.65 69.37,35.63 ; 69.38,35.64 69.37,35.63 ; 69.38,35.64 69.8,36.07 v1(69.8,36.23) ; v1(105.34,98.06) v1(105.34,103.98) ; 24.76,33.78 25.23,33.78 25.23,33.32 ; 39.07,32.02 39.07,32.29 39.35,32.56 v1(39.35,33.09) ; 39.07,32.02 Y7.2 ; 39.07,32.02 C145.2 ; Y3.2 57.39,36.52 56.87,36 v1(56.87,35.89) ; Y3.2 58.14,36.64 58.14,37.62 ; Y3.2 57.39,37.15 C142.1 ; U15.87 v1(103.88,49.93) 103.49,49.54 U15.97 U15.105 ; U15.87 U15.79 ; U15.87 v1(104.7,50.75) U15.77 105.88,50.34 U15.85 ; 57.75,48.44 57.45,48.44 57.45,48.74 ; 102.17,75.69 102.16,75.71 102.07,75.71 101.59,75.24 101,75.24 100.96,75.19 100.38,75.19 99.96,74.78 99.96,72.79 99.27,72.1 99.27,71.67 99.26,71.66 v1(99.29,71.66) ; C267.2 110.07,34.66 ; C267.2 109.13,34.66 ; C267.2 109.6,35.13 ; J16.2 110.96,29.8 ; J16.2 110.96,27.99 ; J16.2 111.86,28.9 ; J16.2 110.05,28.9 ; 70.63,39.27 70.51,39.39 C106.2 ; 77.25,86.97 J23.2 ; J23.2 78.23,87.95 ; J23.2 76.26,87.95 ; J23.2 77.25,88.94 ; 56.03,57.55 55.9,57.42 C25.2 55.91,56.48 R3.2 55.9,57.41 56.03,57.55 56.03,57.55 ; 56.03,57.55 v1(56.03,58.12) ; 22.44,49.82 C154.2 21.97,50.29 ; 39.07,30.69 C145.2 ; C145.2 39.54,31.16 ; C227.2 31.03,27.42 ; C227.2 30.1,27.42 ; C227.2 30.56,26.95 ; 66.88,65.72 U17.25 ; U17.25 65.61,66.99 ; U17.25 68.15,66.99 ; U15.115 U15.105 ; U15.105 U15.95 ; C68.2 104.33,30.54 ; C68.2 103.86,30.07 ; C68.2 103.39,30.54 ; 55.79,34.95 Y3.4 55.62,34.92 55.4,34.71 v1(54.77,34.71) ; 100.69,38.59 L13.2 ; L13.2 100.22,39.06 ; L13.2 101.16,39.06 ; 110.68,47.39 Q4.2 ; Q4.2 111.69,47.39 ; Q4.2 111.18,47.08 110.76,46.65 110.76,46.49 v1(110.74,46.47) ; Q4.2 111.37,47.2 R76.2 R75.2 111.37,44.79 R78.1 ; Q4.2 111.18,47.99 ; v1(75.95,37.29) 76.05,37.29 76.32,37.02 U30.3 ; 69.37,35.63 C133.2 ; C31.2 53.56,20.84 ; C31.2 53.6,20.41 54.23,20.41 v1(54.41,20.22) ; C31.2 54.03,20.37 ; 59.05,49.54 59.05,49.24 58.74,49.24 ; C133.2 69.56,34.92 ; C133.2 68.65,35.51 ; C51.2 59.88,65.72 59.9,65.75 ; 101.57,31.3 C58.2 101.57,30.36 ; 99.17,11.86 C196.2 97.34,11.86 ; 82.25,11.35 82.3,11.3 82.95,11.3 83.53,10.72 ; 57.94,49.24 58.24,49.24 ; 58.24,49.24 58.24,49.54 ; 58.24,49.24 58.24,48.93 ; 58.24,49.24 58.55,49.24 ; C144.2 50.23,35.93 C143.2 50.44,36.56 50.48,36.56 50.76,36.27 v1(50.82,36.27) ; U15.85 U15.75 ; U15.85 U15.95 ; U15.85 106.68,49.54 U15.93 ; 61.16,65.06 C266.2 60.7,65.53 ; Y7.2 38.4,33.54 ; Y7.2 39.14,32.69 ; Y7.2 37.65,32.69 ; Y7.2 38.4,31.85 ; 74.01,44.85 U2.A7 74.36,45.2 ; 80.47,39.58 C203.2 ; C203.2 80.47,40.51 ; C203.2 80.05,40.47 80.05,40.78 v1(79.79,41.04) ; 100.52,37.34 U19.1 100.81,37.85 ; 101.21,55.18 101.21,56.03 ; 101.21,56.03 101.21,56.88 ; U1.B13 59.84,42.34 ; U1.B13 60.15,42.03 ; U1.B13 59.54,42.03 ; 66.51,39.12 C120.2 66.04,39.59 ; T1.14 59.13,12.29 ; T1.14 59.13,9.91 ; T1.14 57.93,11.1 ; v1(30.66,38.85) 30.66,38.21 R141.2 ; v1(25.11,29.66) 24.9,29.88 U31.3 ; 81.4,79.27 81.27,79.39 81.27,79.88 v1(81.15,80) ; 25.59,64.87 25.59,65.03 26.34,65.78 27.61,65.78 v1(27.95,66.13) ; 71.16,51.6 U2.J3 71.5,51.25 ; 61.94,51.63 U1.P16 62.24,51.94 ; 31.82,69.51 TP3.1 ; TP3.1 32.73,70.42 ; TP3.1 30.91,70.42 ; TP3.1 31.82,71.33 ; v1(91.7,37.36) 92.6,38.26 92.79,38.26 P2.9 ; C61.2 102.8,40.53 ; C61.2 102.33,40.06 ; C61.2 103.27,40.06 ; 71.16,44.51 U2.A3 70.81,44.85 ; P2.10 89.27,38.86 ; P2.10 87.62,38.34 ; P2.10 90.92,38.34 ; P2.10 89.27,37.31 v1(89.3,37.28) ; 61.14,47.63 61.45,47.63 ; 61.45,47.63 61.45,47.33 ; 61.45,47.63 61.75,47.63 ; 88.11,53.97 U16.5 88.11,53.31 ; 106.38,37.46 C82.2 105.44,37.46 ; 24.88,49.58 C287.2 23.94,49.58 ; 83.53,10.72 82.95,10.15 82.25,10.15 ; 22.48,46.16 C216.2 22.02,46.63 ; 101.13,73.68 101.1,73.71 100.65,73.71 100.16,73.22 100.16,72.71 99.78,72.32 v1(99.78,72.03) ; 91.22,38.34 P2.9 ; P2.9 92.87,38.86 ; 59.46,58.22 C95.2 59.46,60.05 ; L26.1 82.2,18.41 ; L26.1 81.55,17.85 ; L26.1 82.2,17.3 ; 17.82,42.69 C219.1 17.82,43.62 ; v1(69.95,49.25) 70,49.25 70.36,48.89 U2.F2 ; 94.29,57.6 C157.2 93.82,58.07 ; 15.52,63.12 U4.20 16.53,63.12 ; v1(21.65,32.5) 21.59,32.56 21.59,33.18 C272.2 ; 56.64,41.24 56.64,41.6 57.05,42.01 57.05,42.46 57.43,42.84 57.45,42.84 ; C248.2 30.29,42.37 ; 35.41,67.02 R27.2 ; R27.2 36.34,67.02 ; 36.8,34.9 37.54,34.9 ; 36.8,34.9 36.7,34.9 35.91,34.1 v1(35.86,34.1) ; 36.8,34.9 36.8,35.74 ; 81.47,75.1 81.47,75.57 81,75.57 ; 22.64,69.13 22.64,68.66 22.17,68.66 ; 81.88,78.61 R96.2 82.35,79.08 ; 110.08,34.66 C213.2 ; C213.2 111.02,34.66 ; C213.2 110.55,35.13 ; 28.96,48.64 29.16,48.84 29.16,49 29.57,49.42 ; 101.88,11.08 101.86,11.06 ; 82.23,15.69 C238.2 82.23,14.75 ; 29.61,42.35 29.53,42.27 29.53,41.78 v1(29.61,41.7) ; 84.78,89.54 C296.2 85.25,89.07 ; 76.07,57.61 C91.2 76.07,59.44 ; 35.05,65.98 C265.2 34.58,65.51 ; 109.83,17.09 R214.1 109.36,17.56 ; C174.2 23.66,71.38 v1(24.08,71.8) ; 17.38,52.65 17.36,52.63 R143.2 ; 78.59,79.27 U41.10 80.93,79.27 ; 36.43,30.18 C226.2 36.43,31.63 ; 57.58,65.05 U5.36
  BOTTOM w0.15: U2.H2 70.74,50.07 v1(70.74,49.26) ; U2.F8 75.52,48.49 78.24,48.49 v1(78.58,48.15) ; v1(76.54,45.76) 76.53,45.77 76.51,45.77 76.26,46.02 75.54,46.02 75.18,45.66 ; U2.B2 70.36,45.75 70.67,46.06 71.58,46.06 71.6,46.04 71.71,46.04 72.14,45.61 v1(72.16,45.61)
  BOTTOM w0.2: v1(75.58,51.66) 74.84,51.66 74.45,51.25 U2.J7 ; 61.74,50.44 61.1,50.44 v1(61.09,50.47)
  BOTTOM w0.25: v1(56.33,52.03) 56.33,52.03 57.05,52.03 57.45,52.44 ; U2.B8 75.18,45.66 ; 60.65,53.25 61.06,53.66 v1(61.06,54.37) ; 58.64,41.07 58.64,41.4 ; U1.B13 59.84,42 60.24,41.6 60.24,39.88 59.94,39.58 v1(59.94,39.58)
  BOTTOM w0.3: 93.51,52.99 93.73,52.99 93.98,53.24 94.03,53.24 v1(94.1,53.31) ; 57.09,47.19 56.74,46.84 56.64,46.84 ; 57.09,47.19 57.45,46.84 58.24,46.84 57.87,47.21 v1(57.87,47.28) ; 57.09,47.19 v1(57.09,47.2) ; 57.84,48.83 57.77,48.83 ; 57.84,48.83 57.84,48.84 ; 57.84,48.83 58.24,49.24 ; 57.77,48.83 57.75,48.83 57.75,48.83 57.76,48.83 ; 57.77,48.83 57.75,48.82 57.75,48.75 57.45,48.44 57.13,48.75 57.13,48.84 ; C106.2 69.15,38.74 C115.2 ; v1(51.49,47.19) 51.84,46.84 51.84,46.84 51.85,46.84 ; 61.45,44.44 61.45,44.48 61.36,44.57 61.36,44.59 61.09,44.87 61.09,44.88 v1(61.02,44.95) 60.92,44.95 60.64,45.22 60.64,45.24 ; C283.2 23.7,43.15 23.7,42.94 23.8,42.84 23.91,42.84 C281.2 ; v1(53.05,44.75) 53.11,44.75 53.43,44.44 53.45,44.44 ; 35.05,65.51 35.48,65.95 35.75,65.95 v1(35.98,66.19) ; 35.05,65.51 35.87,65.51 C52.2 ; 35.05,65.51 C265.2 ; v1(110.16,30.45) 109.84,30.45 109.82,30.48 109.49,30.48 ; 56.69,14.34 56.63,14.4 T1.7 ; 58.47,48.93 58.47,48.81 v1(58.6,48.81) ; 58.47,48.93 58.48,48.91 58.56,48.91 ; 58.47,48.93 58.55,48.93 58.64,48.83 U1.K11 57.84,48.84 ; C187.2 66.65,71.81 66.43,72.03 v1(66.34,72.03) ; C212.2 v1(109.18,37.85) ; 21.66,59.42 C160.2 ; 21.66,59.42 U4.4 ; 21.66,59.42 21.66,59.25 v1(21.32,58.91) ; C160.2 22.11,58.3 v1(22.11,58.3) ; C160.2 22.16,59.01 ; 55.05,42.03 54.7,41.69 v1(54.63,41.69) ; v1(57.87,47.28) 58.14,47.55 58.16,47.55 U1.J11 ; v1(57.87,47.28) 58.51,47.28 ; 62.24,42.84 62.24,42.83 62.6,42.47 v1(62.6,42.43) ; v1(103.87,29.49) 103.87,30.53 C68.2 ; v1(26.57,68.85) 26.47,68.75 C190.2 ; U4.3 22.16,59.01 ; 22.16,59.01 22.66,59.51 U4.2 ; U1.U1 50.24,54.56 v1(50.27,54.57) ; v1(20.46,62.34) 20.45,62.37 U4.61 ; 57.58,65.05 C51.2 60.68,65.05 C266.2 ; v1(76.55,84.78) 77.06,84.26 D43.3 77.85,84.26 C207.2 78.78,85.91 C209.2 76.71,85.94 C200.1 76.7,87.41 J23.2 ; 83.6,56.15 83.63,56.12 84,56.12 84,55.62 83.93,55.54 C185.2 ; J12.3 107.81,69.59 v1(107.78,69.63) ; 58.24,49.24 58.65,49.64 v1(58.65,49.71) 58.66,49.71 58.66,49.62 59.05,49.24 58.73,48.91 58.56,48.91 ; 58.24,49.24 58.56,48.91 ; 58.24,49.24 57.84,49.64 v1(57.84,49.64) 57.84,49.63 57.45,49.24 ; U2.A7 v1(73.97,44.47) ; v1(81.64,15.55) 81.74,15.55 82.07,15.22 C238.2 ; C198.2 17.38,52.65 15.64,52.65 15.42,52.87 15.41,52.87 15.23,53.04 v1(15.23,53.04) ; C198.2 18.12,52.32 C150.2 ; C198.2 17.87,52.86 v1(18.69,53.68) ; C188.2 24.77,67.81 v1(25.22,68.27) ; C168.2 17.92,69.66 v1(17.86,69.6) ; C280.2 88.52,58.21 v1(88.51,58.2) ; L25.1 34.05,20.13 ; L25.1 32.93,20.13 ; L25.1 33.49,20.78 ; C161.2 24.48,59.34 v1(24.11,59.72) ; v1(93.01,65.43) 98.25,70.67 98.25,71.68 v1(99.65,73.07) 99.65,75.5 v1(99.99,75.84) 99.99,76.71 v1(99.97,76.73) ; v1(100.69,39.73) 100.69,39.72 L13.2 ; 58.64,41.07 58.64,40.3 v1(58.62,40.28) ; 57.45,49.24 57.84,48.84 ; 57.45,49.24 57.13,48.92 57.13,48.84 ; U32.1 21.59,23.29 21.45,23.15 21.45,21.47 v1(21.48,21.44) ; 60.65,53.25 60.64,53.24 60.64,53.24 ; U15.58 105.04,54.69 105.1,54.62 105.38,54.62 105.34,54.58 v1(105.34,54.25) ; C102.2 13.67,50.03 v1(13.43,49.79) ; v1(92.68,10.32) 92.77,10.41 U20.5 U20.7 ; v1(30.52,32.84) 30.55,32.81 U25.37 ; v1(60.26,51.96) 60.41,51.96 60.64,51.72 U1.P14 ; U41.5 71.63,77.97 71.62,77.96 v1(71.43,77.96) ; v1(55.33,64.78) 55.58,65.02 U5.36 ; v1(25.11,46.68) 25.11,46.68 24.89,46.68 24.77,46.56 24.52,46.56 24.39,46.69 24.37,46.66 C155.2 23.36,46.63 C216.2 ; v1(29.2,28.9) 29.08,29.01 28.53,29.01 C211.2 ; C230.2 34.39,36.43 R147.2 34.76,36.66 35.13,36.29 v1(35.19,36.29) ; v1(99.9,37.73) 100.42,37.73 U19.1 ; 63.05,54.03 63.3,54.03 v1(63.6,53.74) ; v1(98.03,48.05) 98.04,48.04 C261.2 ; 59.05,47.63 U1.J12 58.69,47.28 58.51,47.28 ; C95.2 59.46,60.16 59.37,60.25 59.37,60.32 59.26,60.43 59.26,60.74 v1(59.2,60.8) ; C163.2 25.84,61.19 26.19,60.84 26.76,60.84 ; v1(28.03,67.47) 27.9,67.34 C189.2 ; v1(20.16,67.1) 20.16,67.11 U4.36 ; 26.76,60.84 26.76,60.95 26.93,61.12 v1(26.95,61.12) ; 26.76,60.84 26.96,60.84 27.25,60.56 C164.2 27.98,60.19 v1(28.25,59.92) ; v1(61.09,50.47) 60.66,50.03 U1.M14 ; v1(89.03,52.56) 89.03,52.9 88.29,53.64 U16.5 ; 58.64,41.4 58.64,41.75 58.35,42.03 U1.B11 ; C296.2 85.25,89.6 85.07,89.78 85.02,89.8 84.97,89.83 84.75,90.05 84.72,90.1 v1(84.62,90.1) ; U1.P16 62.25,51.63 v1(62.67,52.06) ; v1(14.26,62.86) 14.26,62.91 14.66,63.31 15.19,63.31 15.41,63.09 16,63.09 U4.20 ; C91.2 76.34,58.53 77.11,57.76 v1(77.11,57.38) ; C91.2 75.76,58.83 75.76,59.22 75.34,59.65 73.54,59.65 73.2,59.31 73.2,58.99 72.46,58.99 ; C91.2 75.76,58.22 75.76,57.83 75.55,57.62 C93.2 ; C165.2 25.86,55.74 25.8,55.69 v1(25.8,55.64) ; U41.10 79.78,79.25 81.4,79.25 ; C97.2 47.47,49.22 47.68,49.01 47.82,49.01 v1(48.05,48.79) ; C229.2 29.84,38.34 30.19,38.69 30.49,38.69 v1(30.66,38.85) ; v1(53.1,50.41) 53.07,50.41 52.64,50.84 ; v1(21.13,67.09) 21.16,67.11 U4.38 ; v1(79.4,73.85) 79.4,74.08 79.76,74.44 U41.16 81.26,75.36 81.47,75.57 81.49,75.54 C273.2 ; v1(37.23,30.73) 37.06,30.91 36.57,30.91 ; 24.29,32.71 24.29,32.92 24.74,33.37 24.81,33.37 25.23,33.78 25.23,34.34 v1(25.33,34.45) ; v1(39.83,65.13) 39.71,65.02 U5.13 36.42,65.02 35.93,65.51 ; C166.1 25.66,67.7 v1(26.14,68.19) ; 36.57,30.91 C226.2 36.3,30.77 R177.2 ; 36.57,30.91 v1(37.22,31.56) ; v1(25.11,49.76) 25.06,49.76 25.02,49.72 24.56,49.72 ; C270.2 v1(112.85,31.55) ; C268.2 v1(109.98,37.87) ; C250.2 30.91,47.25 30.34,46.69 v1(30.27,46.69) ; v1(75.12,85.35) 74.59,85.88 C197.1 ; v1(76.16,54.69) 76.16,55.06 75.96,55.25 ; v1(78.58,50.24) 78.64,50.29 78.64,50.74 v1(78.76,50.85) 78.69,50.93 v1(78.69,51.65) ; U16.1 85.31,52.46 v1(86.17,51.6) ; v1(93.95,56.06) 93.79,56.22 C183.2 93.82,56.74 C157.2 ; C186.2 86.14,57.08 86.12,57.1 86.12,57.03 v1(86.15,57.03) ; 59.05,52.44 59.45,52.84 v1(59.53,52.84) ; v1(31.2,27.19) 31.05,27.34 30.65,27.34 C227.2 ; U2.J3 71.59,51.69 71.59,51.75 v1(71.62,51.77) ; v1(100.9,30.73) 101,30.83 C58.2 ; v1(69.15,69.44) 69.01,69.58 68.31,69.58 68.29,69.6 67.65,69.6 67.63,69.59 U17.23 67.62,68.94 67.62,67.78 66.88,67.04 U17.25 67.13,66.74 U17.9 67.13,64.43 67.11,64.41 v1(67.11,64.27) ; v1(27.04,68.12) 26.49,67.57 C167.2 ; v1(73.6,47.79) 73.98,47.79 74.25,48.06 U2.E7 U2.D8 ; v1(71.34,44.33) 71.34,44.68 71.17,44.85 U2.A3 ; v1(35.04,28.98) 34.95,28.88 C210.2 ; v1(27.45,69.2) 26.75,69.9 C170.2 v1(27.65,70.04) ; 60.64,46.84 60.93,47.12 60.96,47.12 v1(61.06,47.22) 61.12,47.28 61.12,47.31 61.45,47.63 61.78,47.29 61.82,47.29 v1(61.85,47.27) 61.85,47.22 62.24,46.84 62.24,46.84 ; C147.2 22.4,49.58 v1(22.39,49.57) 22.41,49.57 23.1,50.27 C152.2 23.33,50.29 C154.2 ; v1(22.13,67.12) 22.16,67.13 U4.40 22.16,68.18 22.64,68.66 ; R103.2 86.7,55.85 86.15,55.31 v1(86.15,55.05) 86.56,55.05 86.71,54.9 U16.7 86.71,52.33 86.93,52.12 v1(86.91,52.12) ; v1(86.8,8.25) 86.6,8.45 84.98,8.45 U33.1 ; 24.56,49.72 25.08,50.25 25.08,50.49 v1(25.11,50.51) 25.08,50.51 24.97,50.4 C271.2 ; 24.56,49.72 C287.2 ; C110.2 C109.2 62.41,59.61 61.87,60.15 v1(61.87,60.17) ; v1(81.15,80) 81.15,79.63 81.05,79.53 81.05,79.25 ; v1(104.89,39.81) 104.82,39.73 104.82,38.84 103.81,37.83 U19.7 103.81,36.19 U19.33 101.81,35.69 U19.3 ; J12.2 104.86,69.88 v1(104.81,69.93) ; v1(68.58,54.88) 68.58,54.87 69,54.46 U2.N1 ; 57.13,48.84 57.05,48.84 U1.K9 ; R130.2 99.45,40.33 99.45,40.71 v1(99.43,40.72) ; U4.62 21.41,63.63 v1(21.36,63.58) ; 9.38,4.66 J5.3 ; J5.3 14.39,4.66 ; J5.3 11.88,5.57 ; J5.3 11.88,3.75 ; v1(110.16,31.25) 109.49,31.25 ; 58.51,47.28 58.96,46.84 59.05,46.84 ; U41.6 71.32,78.62 v1(71.29,78.59) ; v1(103.34,39.67) 103.19,39.67 C61.2 ; v1(89.61,7.59) 89.62,7.6 C232.2 90.3,8.6 C195.2 89.24,8.64 v1(88.98,8.9) ; U1.M16 62.24,50.16 61.95,50.44 61.74,50.44 ; v1(32.31,42.03) 31.84,41.55 C28.2 31.84,41.42 C26.2 30.5,41.93 R15.2 30.49,42.37 C27.2 29.61,42.35 v1(29.61,41.7) 29.35,41.96 C247.2 ; v1(83.06,17.1) 82.98,17.1 82.75,17.34 82.75,17.66 82.55,17.85 L26.1 82.09,17.97 v1(82.09,18.87) ; v1(112.85,32.4) C159.2 ; C30.2 38.62,41.72 v1(38.77,41.87) ; v1(75.55,50.08) 75.53,50.08 U2.H8 ; C291.2 v1(102.4,86.19) ; U32.9 24.42,25.6 ; U32.9 24.42,22.94 ; U32.9 25.43,24.27 ; v1(62.64,44.75) 62.64,44.84 62.24,45.24 ; v1(12.99,50.22) 12.98,50.23 12.98,51.17 12.94,51.22 12.94,51.25 12.39,51.79 C199.2 ; v1(96.89,12.36) 96.86,12.33 U20.1 97.47,11.35 97.47,11.47 97.56,11.55 97.95,11.55 C196.2 ; 63.05,41.24 62.96,41.16 ; C201.2 81.81,37.22 ; v1(67.48,42.04) 66.92,42.04 C99.2 ; C184.2 95.84,57.78 95.97,57.66 96.84,57.66 96.88,57.69 97.95,57.69 98.15,57.89 v1(98.15,57.9) ; C82.2 v1(105.91,39.78) ; U2.D2 70.44,47.34 70.58,47.34 71.02,47.78 71.02,47.92 U2.E3 71.47,48.06 v1(71.67,47.85)
  BOTTOM w0.5: v1(25.88,39.54) 25.87,39.56 C282.2 25.36,39.68 C85.2 24.7,39.52 25.18,39.04 25.19,39.04 25.34,38.89 25.34,38.84 v1(25.39,38.84) ; v1(17.87,40.9) 17.86,40.91 U28.2 16.74,41.15 C220.2 ; v1(17.1,43.25) 17.2,43.16 C219.1 ; v1(20.25,42.51) 20.25,42.61 20.57,42.93 R173.2 ; v1(28.73,49.21) 28.94,49.42 29.31,49.42 28.96,49.06 28.96,48.64 v1(28.96,48.63) 28.96,48.36 28.62,48.03 ; v1(11.56,21.35) 12.74,21.35 13.54,22.16 C233.2 ; Q15.1 19.56,16.72 20.13,17.29 v1(20.23,17.29) ; C118.2 70.63,39.27 70,39.27 69.72,38.99 v1(69.72,38.61) ; v1(74.8,30.27) 74.78,30.27 74.78,30.26 C208.2 70.23,30.26 70.23,30.26 70.23,30.24 v1(70.23,30.24) ; v1(11.56,23.1) 12.92,23.1 13.54,22.48 C233.2 ; C73.2 20.63,47.97 21.35,47.97 v1(21.38,48.01) ; C233.2 v1(11.6,22.25) ; C15.2 70.92,41.33 70.44,40.85 v1(70.26,40.85) ; 50.24,41.24 49.98,40.97 49.98,40.86 49.95,40.83 v1(49.95,40.83) ; C106.2 68.52,39.39 68.38,39.54 66.93,39.54 66.77,39.7 ; 66.77,39.7 66.63,39.56 66.47,39.56 C120.2 ; 66.77,39.7 66.77,40.23 C122.2 ; v1(98.25,12.94) 98.26,12.94 C196.2 ; C33.2 29.57,49.42 ; v1(77.15,34.92) 77.14,34.93 77.14,35.34 77.94,36.14 U22.11 80.91,36.14 v1(80.92,36.13) ; C283.2 23.35,44.14 v1(23.01,44.47) ; v1(56.64,40.03) 56.64,41.24 ; C231.2 v1(18.98,25.35) ; v1(62.75,40.45) 62.96,40.67 62.96,41.16 ; 81.81,37.22 v1(81.81,38.05)
  vias: v1(0.55,12.66) v1(0.55,1.66) v1(1.02,56.08) v1(1.02,52.08) v1(1.02,48.08) v1(1.02,44.08) v1(1.02,40.08) v1(1.02,36.08) v1(1.02,32.08) v1(1.02,15.08) v1(1.22,79.93) v1(1.22,75.93) v1(1.22,71.93) v1(1.21,59.96) v1(2.02,58.08) v1(2.02,54.08) v1(2.02,50.08) v1(2.02,46.08) v1(2.02,42.08) v1(2.02,38.08) v1(2.02,34.08) v1(2.02,30.08) v1(2.02,17.08) v1(2.11,71.31) v1(2.22,77.93) v1(2.22,73.93) v1(3.02,56.08) v1(3.02,52.08) v1(3.02,48.08) v1(3.02,44.08) v1(3.02,40.08) v1(3.02,36.08) v1(3.02,32.08) v1(3.02,19.08) v1(3.02,15.08) v1(3.22,79.93) v1(3.22,75.93) v1(3.22,71.93) v1(3.21,59.96) v1(3.55,1.66) v1(4.02,58.08) v1(4.02,54.08) v1(4.02,50.08) v1(4.02,46.08) v1(4.02,42.08) v1(4.02,38.08) v1(4.02,34.08) v1(4.02,30.08) v1(4.02,17.08) v1(4.22,77.93) v1(4.22,73.93) v1(4.5,71.43) v1(5.02,67.08) v1(5.02,64.08) v1(5.02,56.08) v1(5.02,52.08) v1(5.02,48.08) v1(5.02,44.08) v1(5.02,40.08) v1(5.02,36.08) v1(5.02,32.08) v1(5.02,23.08) v1(5.02,19.08) v1(5.02,15.08) v1(5.22,79.93) v1(5.22,75.93) v1(5.22,71.93) v1(5.21,59.96) v1(6.02,66.08) v1(6.02,62.08) v1(6.02,58.08) v1(6.02,54.08) v1(6.02,50.08) v1(6.02,46.08) v1(6.02,42.08) v1(6.02,38.08) v1(6.02,34.08) v1(6.02,31.08) v1(6.02,25.08) v1(6.02,21.08) v1(6.02,17.08) v1(6.22,77.93) v1(6.22,73.93) v1(7.02,67.08) v1(7.02,64.08) v1(7.02,56.08) v1(7.02,52.08) v1(7.02,48.08) v1(7.02,44.08) v1(7.02,40.08) v1(7.02,36.08) v1(7.02,32.08) v1(7.02,23.08) v1(7.02,19.08) v1(7.02,15.08) v1(7.22,79.93) v1(7.22,75.93) v1(7.22,71.93) v1(7.21,59.96) v1(8.02,66.08) v1(8.02,62.08) v1(8.02,58.08) v1(8.02,54.08) v1(8.02,50.08) v1(8.02,46.08) v1(8.02,42.08) v1(8.02,38.08) v1(8.02,34.08) v1(8.02,31.08) v1(8.02,25.08) v1(8.02,21.08) v1(8.02,17.08) v1(8.22,77.93) v1(8.22,73.93) v1(8.55,12.66) v1(8.87,48) v1(8.87,44) v1(8.87,40) v1(8.87,36) v1(8.87,32) v1(9.02,67.08) v1(9.02,64.08) v1(9.02,60.08) v1(9.02,56.08) v1(9.02,52.08) v1(9.02,23.08) v1(9.02,19.08) v1(9.22,79.93) v1(9.22,75.93) v1(9.22,71.93) v1(9.87,50) v1(9.87,46) v1(9.87,42) v1(9.87,38) v1(9.87,34) v1(10.02,66.08) v1(10.02,62.08) v1(10.02,58.08) v1(10.02,54.08) v1(10.02,31.08) v1(10.02,25.08) v1(10.02,21.08) v1(10.22,77.93) v1(10.22,73.93) v1(10.87,48) v1(10.87,44) v1(10.87,40) v1(10.87,36) v1(10.87,32) v1(11.02,67.08) v1(11.02,64.08) v1(11.02,60.08) v1(11.02,56.08) v1(11.02,52.08) v1(11.12,25.76) v1(11.22,79.93) v1(11.22,75.93) v1(11.22,71.93) v1(12.02,65.3) v1(12.02,46.08) v1(12.02,42.08) v1(12.02,38.08) v1(12.02,34.08) v1(12.22,77.93) v1(12.22,73.93) v1(12.88,67.67) v1(13.07,60.11) v1(13.02,44.08) v1(13.22,79.93) v1(13.22,75.93) v1(13.22,71.93) v1(13.63,63.19) v1(13.65,39.95) v1(13.95,38.95) v1(13.99,35.72) v1(14.04,32.09) v1(14.07,30.88) v1(14.22,77.93) v1(14.29,70.15) v1(14.2,55.96) v1(15.05,75.95) v1(15.02,44.08) v1(15.22,79.93) v1(15.28,78.47) v1(15.22,71.93) v1(15.51,69) v1(16.34,79.94) v1(16.9,38.51) v1(17.07,77.72) v1(17.04,75.83) v1(17.01,36.86) v1(17.15,72) v1(17.48,34.42) v1(17.72,49.16) v1(17.82,3.75) v1(18.05,80.96) v1(18.16,41.89) v1(18.2,8.86) v1(18.2,49.71) v1(18.27,27.78) v1(18.37,79) v1(18.45,76.12) v1(18.42,28.88) v1(18.98,74) v1(19.05,36.52) v1(19.45,40.88) v1(19.42,37.68) v1(19.44,9.54) v1(19.58,77.87) v1(19.63,76.4) v1(19.62,44.68) v1(19.88,38.83) v1(20.43,71.53) v1(20.68,79.5) v1(20.69,78.45) v1(20.99,38.74) v1(21.08,37.79) v1(21.07,27.08) v1(21.05,9) v1(21.3,18.45) v1(21.61,3.67) v1(21.79,44.72) v1(22.2,36.35) v1(22.25,6.15) v1(22.38,73.74) v1(22.45,8.25) v1(22.65,17.05) v1(22.65,12.9) v1(22.7,75.75) v1(23.41,74.81) v1(23.51,78.81) v1(23.52,72.39) v1(23.97,24.73) v1(24.52,24.02) v1(24.52,23.44) v1(24.55,6.4) v1(24.73,71.76) v1(24.8,1.11) v1(24.87,24.73) v1(24.91,79.17) v1(24.91,75.17) v1(25.2,31.91) v1(25.16,3.73) v1(25.3,54.7) v1(25.51,80.81) v1(25.65,18.65) v1(25.91,77.17) v1(26.01,44.5) v1(26.15,73) v1(26.19,1.21) v1(26.59,26.91) v1(26.91,79.17) v1(26.91,75.17) v1(27.51,80.81) v1(27.59,1.05) v1(27.87,46.46) v1(27.91,77.17) v1(27.99,73.06) v1(28.1,21.75) v1(28.1,5.85) v1(28.12,70.94) v1(28.3,55.55) v1(28.6,27.65) v1(28.91,79.17) v1(28.91,75.17) v1(29.12,68.94) v1(29.2,4.5) v1(29.51,80.81) v1(29.85,27.1) v1(29.91,77.17) v1(29.99,73.06) v1(30.12,70.94) v1(30.44,1.21) v1(30.91,79.17) v1(30.91,75.17) v1(30.98,58.27) v1(31.05,22.4) v1(31.15,24.8) v1(31.51,80.81) v1(31.91,77.17) v1(31.99,73.06) v1(32.07,28.58) v1(32.45,23.4) v1(32.5,27.05) v1(32.5,24.75) v1(32.91,79.17) v1(32.91,75.17) v1(33.2,36.04) v1(33.32,1.08) v1(33.51,80.81) v1(33.6,41.05) v1(33.76,23.53) v1(33.91,77.17) v1(33.99,73.06) v1(34.76,24.48) v1(34.91,79.17) v1(34.91,75.17) v1(35.01,22.03) v1(35.51,80.81) v1(35.91,77.17) v1(35.99,73.06) v1(36.03,62.98) v1(36.51,1.08) v1(36.91,79.17) v1(36.91,75.17) v1(37,40.1) v1(37.05,20.08) v1(37.1,29.73) v1(37.2,22.23) v1(37.51,80.81) v1(37.5,56.27) v1(37.51,27.18) v1(37.91,77.17) v1(38.8,26.58) v1(38.85,24.28) v1(38.91,79.17) v1(38.91,75.17) v1(39.26,20.18) v1(39.51,80.81) v1(39.85,1.12) v1(39.91,77.17) v1(39.98,69.03) v1(40.16,38.92) v1(40.26,24.93) v1(40.45,22.68) v1(40.91,79.17) v1(40.91,75.17) v1(41.26,18.83) v1(41.34,37.87) v1(41.51,80.81) v1(41.91,77.17) v1(41.95,35.2) v1(42.04,68.45) v1(42.12,42.74) v1(42.15,23.55) v1(42.37,1.05) v1(42.75,56.91) v1(42.91,79.17) v1(42.91,75.17) v1(42.94,7.5) v1(43.05,33.9) v1(43.08,4.26) v1(43.35,20.13) v1(43.44,69.49) v1(43.43,58.74) v1(43.51,80.81) v1(43.91,77.17) v1(43.9,35.63) v1(43.92,13.31) v1(44,22.3) v1(44.16,31.78) v1(44.12,17.84) v1(44.21,15.79) v1(44.45,18.8) v1(44.58,44.28) v1(44.91,79.17) v1(44.91,75.17) v1(45.51,80.81) v1(45.57,2.73) v1(45.7,31.3) v1(45.66,0.92) v1(45.73,69.54) v1(45.85,33.15) v1(45.91,77.17) v1(45.91,23.53) v1(46.67,36.24) v1(46.91,79.17) v1(46.91,75.17) v1(46.95,24.85) v1(47.25,22.25) v1(47.45,29.4) v1(47.45,26.9) v1(47.51,80.81) v1(47.73,43.27) v1(47.91,77.17) v1(48.05,30.95) v1(48.32,40.03) v1(48.55,0.9) v1(48.65,28.15) v1(48.65,25.75) v1(48.85,22.25) v1(48.91,79.17) v1(48.91,75.17) v1(49.05,23.65) v1(49.14,2.91) v1(49.22,66.97) v1(49.36,43.85) v1(49.51,80.81) v1(49.55,33.3) v1(49.91,77.17) v1(50.25,23.6) v1(50.75,27.03) v1(50.75,25.4) v1(50.75,22.3) v1(50.81,68.49) v1(50.91,79.17) v1(50.91,75.17) v1(51.05,33.5) v1(51.51,80.81) v1(51.78,2.9) v1(51.87,68.07) v1(51.91,77.17) v1(52.09,36.37) v1(52.15,25.65) v1(52.23,0.92) v1(52.5,23.8) v1(52.7,26.85) v1(52.65,22.25) v1(52.74,33.62) v1(52.91,79.17) v1(52.91,75.17) v1(52.92,62.17) v1(52.98,38.62) v1(53.51,80.81) v1(53.91,77.17) v1(54.03,60.17) v1(54.1,25.05) v1(54.78,2.15) v1(54.91,79.17) v1(54.91,75.17) v1(54.97,0.92) v1(55.35,20.08) v1(55.51,80.81) v1(55.53,26.09) v1(55.67,37.8) v1(55.83,31.14) v1(55.91,77.17) v1(55.91,59.11) v1(56.45,18.78) v1(56.58,12.31) v1(56.6,54.95) v1(56.7,5.13) v1(56.91,79.17) v1(56.91,75.17) v1(57.51,80.81) v1(57.76,18.25) v1(57.91,77.17) v1(57.99,0.93) v1(58.75,20.18) v1(58.91,79.17) v1(58.91,75.17) v1(59.31,58.03) v1(59.51,80.81) v1(59.91,77.17) v1(60.13,26.19) v1(60.3,22.78) v1(60.35,17.83) v1(60.64,60.09) v1(60.91,79.17) v1(60.91,75.17) v1(61.35,0.99) v1(61.43,34.37) v1(61.51,80.81) v1(61.57,19.34) v1(61.91,77.17) v1(61.96,32.44) v1(62.08,71.59) v1(62.27,31.77) v1(62.6,15.63) v1(62.85,69.1) v1(63.2,79.01) v1(63.2,75.01) v1(63.16,16.93) v1(63.29,88.92) v1(63.34,86.23) v1(63.55,83.23) v1(63.8,80.66) v1(63.88,69.1) v1(64.2,77.01) v1(64.41,58.91) v1(64.44,1.05) v1(64.97,59.78) v1(65.15,83) v1(65.2,79.01) v1(65.2,75.01) v1(65.45,16.53) v1(65.55,58.91) v1(65.8,80.66) v1(66.2,77.01) v1(66.17,26.93) v1(66.28,59.78) v1(66.75,22.09) v1(66.85,58.87) v1(67.2,79.01) v1(67.2,75.01) v1(67.11,15.28) v1(67.57,59.75) v1(67.55,1.12) v1(67.8,80.66) v1(68.09,58.85) v1(68.2,77.01) v1(68.25,16.63) v1(68.73,59.76) v1(68.86,15.13) v1(69.15,83) v1(69.15,79) v1(69.11,31.34) v1(69.13,30.57) v1(69.28,58.88) v1(69.69,25.03) v1(69.78,89.14) v1(69.86,59.75) v1(70.23,41.88) v1(70.24,30.84) v1(70.24,29.69) v1(70.38,58.81) v1(70.37,1.08) v1(70.43,42.53) v1(70.41,20.39) v1(70.95,59.76) v1(70.91,17.13) v1(71,14.78) v1(71.38,58.81) v1(71.45,64.24) v1(71.5,27) v1(71.78,8.72) v1(72.07,59.81) v1(73.07,59.88) v1(73.05,44.3) v1(73.24,89.58) v1(73.91,64.25) v1(73.91,16.93) v1(73.95,15.88) v1(74,14.98) v1(74.62,1.02) v1(75.41,30.27) v1(75.75,78.45) v1(76.09,89.64) v1(76.08,30.27) v1(76.12,59.91) v1(76.18,25.03) v1(76.9,36.58) v1(77,78.55) v1(77.18,26.86) v1(77.25,68.29) v1(77.44,43.24) v1(77.96,44) v1(78.19,65.5) v1(78.52,47) v1(78.51,45.92) v1(78.7,0.99) v1(78.78,25.97) v1(79.23,89.54) v1(79.26,52.37) v1(79.38,51.05) v1(79.47,46.93) v1(79.83,54.83) v1(79.98,69.39) v1(80.14,53.72) v1(80.16,52.59) v1(80.16,51.56) v1(80.16,50.43) v1(80.19,48.93) v1(80.16,8.72) v1(80.16,1.8) v1(80.26,26.93) v1(80.6,60.15) v1(80.77,89.55) v1(81,71.9) v1(81.14,28.3) v1(81.6,41) v1(82.22,44.34) v1(82.9,72) v1(82.95,60.45) v1(83,36.6) v1(83.15,41) v1(83.36,1.9) v1(83.34,1.02) v1(83.42,51.68) v1(83.65,56.15) v1(83.85,42.6) v1(83.84,11.31) v1(83.83,10.15) v1(83.97,61.87) v1(84.05,31.31) v1(84.03,25.86) v1(84.01,10.72) v1(84.45,44.75) v1(84.6,26.88) v1(84.77,11.24) v1(85.25,80.35) v1(85.73,48.13) v1(85.81,6.12) v1(86,24.41) v1(86.1,64.01) v1(86.27,77.59) v1(86.58,76.33) v1(86.52,61.73) v1(86.73,50.38) v1(86.77,46.58) v1(86.9,34.15) v1(86.86,31) v1(87.41,35.6) v1(87.58,48.13) v1(87.51,5.93) v1(87.65,62.84) v1(87.78,20.54) v1(88.06,66.15) v1(88.05,25.95) v1(88.58,11.58) v1(88.87,13.91) v1(89.1,76.2) v1(89.11,64.3) v1(89.35,16.63) v1(89.48,47.13) v1(89.62,83.31) v1(89.71,45.07) v1(90.06,52.03) v1(90.73,48.93) v1(91.07,81.07) v1(91.46,1.06) v1(91.55,25.95) v1(91.8,102.89) v1(91.87,100.36) v1(91.8,97.98) v1(91.9,95.09) v1(91.83,92.36) v1(91.87,89.08) v1(92.08,44.68) v1(92.88,23.28) v1(93.08,48.03) v1(93.4,24.6) v1(94.02,96.44) v1(94.12,99.17) v1(94.12,93.84) v1(94.21,90.44) v1(94.45,68.07) v1(95.27,103.6) v1(95.4,23.34) v1(95.62,1.03) v1(95.88,69.5) v1(96,25.9) v1(96.04,101.16) v1(96.6,33.4) v1(97.26,103.47) v1(97.23,89.38) v1(97.39,29.68) v1(97.3,24.6) v1(97.42,91.75) v1(97.75,76.22) v1(97.74,74.12) v1(98.23,98.97) v1(98.65,45.97) v1(98.69,23.15) v1(98.66,19.71) v1(98.81,31.09) v1(99.55,25.45) v1(99.7,97.44) v1(99.61,90.4) v1(99.67,44.05) v1(99.86,93.55) v1(100.02,28.24) v1(100.15,103.47) v1(100.14,32.6) v1(100.28,100.91) v1(100.41,14.4) v1(101.34,98.78) v1(101.31,95.44) v1(101.41,91.62) v1(102.12,31.32) v1(102.2,20.4) v1(102.41,23.16) v1(102.54,28.91) v1(102.75,22.1) v1(102.85,97.18) v1(102.82,93.48) v1(103.13,75.62) v1(103.13,72.66) v1(103.36,31.06) v1(103.64,101.83) v1(103.77,90.81) v1(103.71,62.12) v1(104.07,103.31) v1(104.23,99.04) v1(104.28,28.23) v1(104.39,42.37) v1(104.56,16.91) v1(104.73,101.88) v1(104.84,31.28) v1(105.04,38.16) v1(105.12,64.68) v1(105.18,63.45) v1(105.3,82.22) v1(105.32,80.45) v1(105.42,61.94) v1(105.47,60.18) v1(105.52,57.88) v1(105.52,55.62) v1(105.63,76.27) v1(105.65,43.4) v1(105.65,20.5) v1(105.84,86.15) v1(106,78.66) v1(106.14,101.34) v1(106.25,90.72) v1(106.36,88.9) v1(106.31,70.58) v1(106.32,6.95) v1(106.59,60.96) v1(106.58,56.84) v1(106.59,38.19) v1(106.62,58.88) v1(106.61,54.91) v1(106.64,37.28) v1(106.72,62.58) v1(107.22,64.54) v1(107.33,18.87) v1(107.47,61.5) v1(107.57,59.12) v1(107.68,72.12) v1(107.62,56.59) v1(107.78,77.45) v1(107.73,74.6) v1(107.81,99.56) v1(107.81,90.09) v1(107.91,95.37) v1(107.98,66.22) v1(108.04,86.72) v1(108.04,80.5) v1(108.14,84.12) v1(108.2,64.26) v1(108.1,1.03) v1(108.25,63.12) v1(108.46,43.42) v1(108.95,92.73) v1(108.97,55.4) v1(108.97,54.26) v1(109.08,60.53) v1(109.14,104.33) v1(109.11,87.76) v1(109.11,85.36) v1(109.18,78.84) v1(109.18,73.25) v1(109.18,70.46) v1(109.12,67.35) v1(109.12,64.77) v1(109.12,62.38) v1(109.21,102.05) v1(109.21,97.59) v1(109.22,82.33) v1(109.23,75.9) v1(109.53,41.54) v1(109.8,5.25) v1(110.06,53.33) v1(110.14,3.09) v1(110.33,0.92) v1(110.5,6.6) v1(111.14,51.74) v1(112.23,53.22) v1(112.34,16.69) v1(112.8,49.72) v1(112.75,1.12) v1(113.23,51.46) v1(113.99,47.99) v1(114.04,45.26) v1(114.41,53.18) v1(114.43,18.43) v1(114.82,49.72) v1(115.26,46.49) v1(115.42,20.58) v1(115.62,51.27) v1(116.22,53.38) v1(116.22,48.14) v1(116.24,44.85) v1(116.47,27.24) v1(117.22,25.69) v1(117.48,52.11) v1(118,46.78) v1(118.59,49.97) v1(118.83,53.38) v1(119.04,45.07) v1(119.79,48.49) v1(119.95,7.6) v1(120.18,51.91) v1(120.3,47.04) v1(120.87,53.34) v1(121.39,49.99) v1(122.38,52.01) v1(122.56,45.04) v1(122.55,42.66) v1(122.55,40.66) v1(122.55,37.66) v1(122.55,29.66) v1(122.58,25.29) v1(122.62,27.4) v1(122.65,14.31) v1(122.65,13.01) v1(122.78,53.4) v1(122.76,48.31) v1(122.75,11.15) v1(122.74,8.75) v1(122.74,4.44)
VBUS_BOT: length 22.8
  TOP w0.3: C235.1 27.09,23.45 27.45,23.8 27.45,23.85 27.6,24 v1(28.1,24)
  INT1 w0.5: v1(28.1,24) 29.05,23.05 29.05,21.05 28.95,20.94 28.95,7.28 v1(29.3,6.92)
  BOTTOM w0.3: U32.6 27.51,24.59 v1(28.1,24)
  BOTTOM w0.5: v1(29.3,6.92) 29.6,6.92 29.62,6.9 30.19,6.9 L22.1
